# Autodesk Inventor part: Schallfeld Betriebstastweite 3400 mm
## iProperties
Shininess: 20.0
Length Units: 11269
Angle Units: 11279
Time Units: 11290
Mass Units: 11283
Length Display Precision: 2
Angle Display Precision: 2
Part Number: Schallfeld Betriebstastweite 3400 mm
Material: Lexan (klar)
Document SubType Name: Modellieren
Description: Schallfeld 3,4m
Checked By: Alves
Created: 2005-08
Designer: Ohle
Manufacturer: Standard
Standards Organization: Custom
Density: 0.0
Volumn: 0.0
Area: 0.0
PropertySet Name: Model Information
Control State: 0
Master: False
Checked Out: False
Last Check In By: Kramp
Last Check In Date: 2005-08-11
ME: ST
Title: Schallfelder
Author: Ohle
Comments: keine Bemerkung
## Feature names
1. Blindzone_Aussenglocke [Revolution]
